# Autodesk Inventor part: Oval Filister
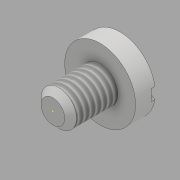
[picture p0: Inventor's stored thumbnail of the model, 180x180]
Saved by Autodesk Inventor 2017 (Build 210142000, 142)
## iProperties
Created: 2016-06
Part Number: Oval Filister
Material: Generic
Document SubType Name: Modeling
Designer: CADCIM
Density: 1 g/cm^3
Appearance: Default
Author: CADCIM
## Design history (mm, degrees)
sketch "Sketch1"
  geometry: 1 further point
sketch "Sketch2"
  geometry: C1 r 3 at (0, 0); 1 further point
  constraints: 1 centre point, 1 coincident
  dimensions: "d0" = 6 diameter of C1
extrude "Extrusion1" new body sketch "Sketch2" distance "d1" = 8; taper "d2" = 0 deg
sketch "Sketch3"
  geometry: 1 further point
sketch "Sketch4"
  geometry: L1 (8, 0)-(8, -6); L2 (8, -3)-(8, 3) reference; L3 (8, -6)-(11.35, -6); L4 (12.6, 0)-(8, 0); A1 r 15.025 centre (-2.425, 0) between (11.35, -6) and (12.6, 0); 2 further points
  constraints: 6 end point, 2 midpoint, 2 point on circle, 1 centre point, 1 horizontal, 1 horizontal alignment, 1 perpendicular, 1 point on line, 1 vertical
  dimensions: "d3" = 6 distance of L1.start L1.end; "d4" = 4.6 distance of L4.start L1.start; "d5" = 1.25 horizontal distance of L3.end L4.start
revolve "Revolution1" sketch "Sketch4" stored, may be unused: angle "d6" = 90 deg
workplane "Work Plane1"
sketch "Sketch5"
  geometry: L1 (6.611, -0.95)-(-6.611, -0.95); L2 (-6.611, -0.95)-(-6.611, 0.95); L3 (-6.611, 0.95)-(6.611, 0.95); L4 (6.611, 0.95)-(6.611, -0.95); L5 (6.611, 0)-(-6.611, 0); 2 further points
  constraints: 10 end point, 3 midpoint, 2 parallel, 1 coincident, 1 horizontal, 1 perpendicular
  dimensions: "d8" = 1.9 distance of L3.end L1.start
extrude "Extrusion2" cut sketch "Sketch5" distance "d9" = 1.9; taper "d10" = 0 deg
thread "Thread1" dims "d11" = 10, "d12" = 0
chamfer "Chamfer1" distance "d13" = 1; stored, may be unused: second distance "d14" = 2, angle "d15" = 45 deg
body "Solid1"
other parameters: "d7" = -4.6
